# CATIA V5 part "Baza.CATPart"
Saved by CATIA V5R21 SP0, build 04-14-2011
Part number: BAZA
Bounding box of the stored display mesh (mm): x -150 to 150, y -149.807 to 149.807, z 0 to 80
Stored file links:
  C:\Users\MIRCEA\Desktop\PRRO\CATIAV5\Baza.CATPart
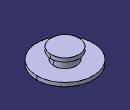
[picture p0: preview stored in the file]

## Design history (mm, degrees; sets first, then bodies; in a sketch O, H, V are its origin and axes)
Body1 (main body)
  Sketch1 on xy-plane, origin (0, 0, 0), H (1, 0, 0), V (0, 1, 0)
    circle A1 centre (0, 0) radius 150
    radius A1 = 150
  Pad1: profile Sketch1, direction (0, 0, 1), length 20
  Sketch2 on xy-plane, origin (0, 0, 0), H (1, 0, 0), V (0, 1, 0)
    circle A1 centre (0, 0) radius 60
    radius A1 = 60
  Pad2: profile Sketch2, direction (0, 0, 1), length 60
  Plane1: type Offset, RefPlane xy-plane, Offset 60
  Sketch3 on Plane1, origin (0, 0, 60), H (1, 0, 0), V (0, 1, 0)
    circle A1 centre (0, 0) radius 75
    radius A1 = 75
  Pad3: profile Sketch3, direction (0, 0, 1), length 20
